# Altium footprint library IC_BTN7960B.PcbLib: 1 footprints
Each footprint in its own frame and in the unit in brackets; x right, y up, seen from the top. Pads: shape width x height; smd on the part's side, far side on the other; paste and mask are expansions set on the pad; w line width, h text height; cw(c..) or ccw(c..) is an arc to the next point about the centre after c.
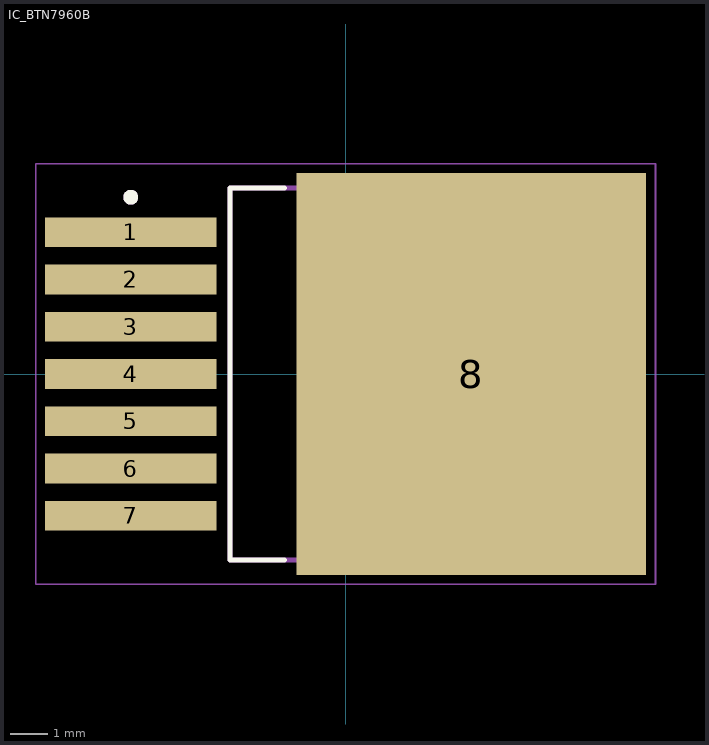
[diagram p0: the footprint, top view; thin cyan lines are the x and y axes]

## IC_BTN7960B [mm]
pads (8):
  rect 4.6x0.8 smd: 1(-5.775,3.81) 2(-5.775,2.54) 3(-5.775,1.27) 4(-5.775,0) 5(-5.775,-1.27) 6(-5.775,-2.54) 7(-5.775,-3.81)
  rect 9.4x10.8 smd paste-6: 8(3.375,0)
Top Overlay:
  circle w0.2: c-5.775,4.75 r0.1
  lines w0.127: -1.639,-5 -3.105,-5 -3.105,5 -1.639,5
Top Paste:
  region: 0.26,-5.155 -1.03,-5.155 -1.03,-3.845 0.26,-3.845
  region: 0.26,-3.355 -1.03,-3.355 -1.03,-2.045 0.26,-2.045
  region: 0.26,-1.555 -1.03,-1.555 -1.03,-0.245 0.26,-0.245
  region: 0.26,3.845 -1.03,3.845 -1.03,5.155 0.26,5.155
  region: 0.26,2.045 -1.03,2.045 -1.03,3.355 0.26,3.355
  region: 0.26,0.245 -1.03,0.245 -1.03,1.555 0.26,1.555
  region: 2.14,-5.155 0.85,-5.155 0.85,-3.845 2.14,-3.845
  region: 2.14,-3.355 0.85,-3.355 0.85,-2.045 2.14,-2.045
  region: 2.14,-1.555 0.85,-1.555 0.85,-0.245 2.14,-0.245
  region: 2.14,3.845 0.85,3.845 0.85,5.155 2.14,5.155
  region: 2.14,2.045 0.85,2.045 0.85,3.355 2.14,3.355
  region: 2.14,0.245 0.85,0.245 0.85,1.555 2.14,1.555
  region: 7.78,-5.155 6.49,-5.155 6.49,-3.845 7.78,-3.845
  region: 7.78,-3.355 6.49,-3.355 6.49,-2.045 7.78,-2.045
  region: 7.78,-1.555 6.49,-1.555 6.49,-0.245 7.78,-0.245
  region: 7.78,3.845 6.49,3.845 6.49,5.155 7.78,5.155
  region: 7.78,2.045 6.49,2.045 6.49,3.355 7.78,3.355
  region: 7.78,0.245 6.49,0.245 6.49,1.555 7.78,1.555
  region: 5.9,-5.155 4.61,-5.155 4.61,-3.845 5.9,-3.845
  region: 5.9,-3.355 4.61,-3.355 4.61,-2.045 5.9,-2.045
  region: 5.9,-1.555 4.61,-1.555 4.61,-0.245 5.9,-0.245
  region: 5.9,3.845 4.61,3.845 4.61,5.155 5.9,5.155
  region: 5.9,2.045 4.61,2.045 4.61,3.355 5.9,3.355
  region: 5.9,0.245 4.61,0.245 4.61,1.555 5.9,1.555
  region: 4.02,-5.155 2.73,-5.155 2.73,-3.845 4.02,-3.845
  region: 4.02,-3.355 2.73,-3.355 2.73,-2.045 4.02,-2.045
  region: 4.02,-1.555 2.73,-1.555 2.73,-0.245 4.02,-0.245
  region: 4.02,3.845 2.73,3.845 2.73,5.155 4.02,5.155
  region: 4.02,2.045 2.73,2.045 2.73,3.355 4.02,3.355
  region: 4.02,0.245 2.73,0.245 2.73,1.555 4.02,1.555
Mechanical 13:
  circle w0.2: c-5.775,4.75 r0.1
  lines w0.127: -3.105,-5 -3.105,5 6.155,5 6.155,-5 -3.105,-5
Mechanical 15:
  lines w0.05: -8.325,-5.65 -8.325,5.65 8.325,5.65 8.325,-5.65 -8.325,-5.65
